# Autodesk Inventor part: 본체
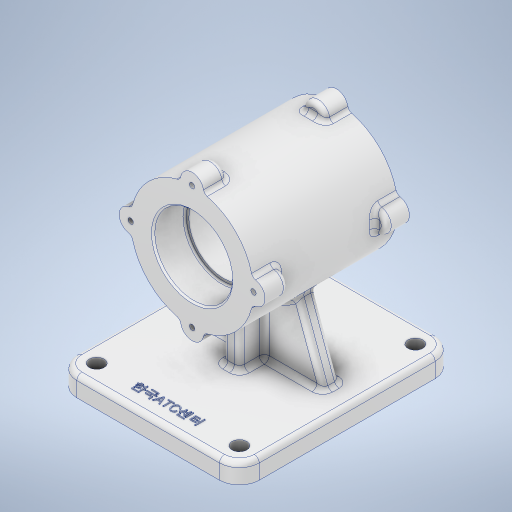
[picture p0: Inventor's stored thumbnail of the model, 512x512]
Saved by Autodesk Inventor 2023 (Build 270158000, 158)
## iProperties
Created: 2023-08
Part Number: 본체
Material: 알루미늄 6061
Document SubType Name: Modeling
Designer: asung
Density: 2.7 g/cm^3
Appearance: 알루미늄 - 평지
Mass: 1215.39 g
Surface Area: 796.917 cm^2
Volume: 450.145 cm^3
Author: asung
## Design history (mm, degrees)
sketch "스케치1"
  geometry: L1 (53, 55)-(-53, 55); L2 (-65, 43)-(-65, -43); L3 (-53, -55)-(53, -55); L4 (65, -43)-(65, 43); L5 (65, 55)-(-65, -55); L6 (-65, 55)-(65, -55); A1 r 12 centre (53, -43) between (53, -55) and (65, -43); A2 r 12 centre (53, 43) between (65, 43) and (53, 55); A3 r 12 centre (-53, 43) between (-53, 55) and (-65, 43); A4 r 12 centre (-53, -43) between (-65, -43) and (-53, -55); 1 further point
  constraints: 12 end point, 8 point on circle, 8 point on line, 8 tangent, 4 centre point, 3 equal radius, 2 midpoint, 2 parallel, 1 horizontal, 1 perpendicular
  dimensions: "d0" = 130 distance of L6.end L5.end; "d1" = 110 distance of L5.end L6.start; "d2" = 12 radius of A1
extrude "돌출1" new body sketch "스케치1" distance "d3" = 12; taper "d4" = 0 deg
fillet "모깎기1" dims "d5" = 3
sketch "스케치2"
  geometry: A1 r 9 centre (53, -43) between (53, -52) and (62, -43) reference; A2 r 9 centre (-53, -43) between (-62, -43) and (-53, -52) reference; A3 r 9 centre (-53, 43) between (-53, 52) and (-62, 43) reference; A4 r 9 centre (53, 43) between (62, 43) and (53, 52) reference; 5 further points
  constraints: 4 coincident
hole "구멍1" sketch "스케치2" at (53, -43), (-53, -43), (-53, 43), (53, 43) diameter "d6" = 9; stored, may be unused: countersink angle "d10" = 90 deg, drill point angle "d12" = 118 deg; dims "d7" = 6, "d8" = 4, "d9" = 2, "d11" = 8
node "작업 평면1"
sketch "스케치3"
  geometry: L1 (106, 0)-(0, 0) reference; L2 (58, 0)-(58, 82); L3 (-12, 0)-(-12, 9) reference; L4 (14.5, 82)-(101.5, 82); L5 (14.5, 82)-(14.5, 119); L6 (14.5, 119)-(101.5, 119); L7 (101.5, 119)-(101.5, 82); 1 further point
  constraints: 10 end point, 2 perpendicular, 2 vertical, 1 horizontal, 1 midpoint, 1 point on line
  dimensions: "d14" = 82 distance of L2.end L2.start; "d15" = 70 distance between parallel lines of L3 L2; "d16" = 87 distance of L4.start L4.end; "d17" = 37 distance of L4.start L5.end
revolve "회전1" sketch "스케치3" stored, may be unused: angle "d18" = 90 deg
node "작업 평면2"
sketch "스케치4"
  geometry: C1 r 37 at (0, 0) reference; C2 r 7 at (0, 37); 2 further points
  constraints: 1 centre point, 1 vertical alignment, 1 other
  dimensions: "d19" = 7 radius of C2
extrude "돌출2" join sketch "스케치4" distance "d23" = 14; taper "d24" = 0 deg
fillet "모깎기2" dims "d25" = 3
fillet "모깎기3" dims "d26" = 3
sketch "스케치5"
  geometry: A1 r 7 centre (0, 0) between (6.889, 1.239) and (-6.889, 1.239) reference; 2 further points
  constraints: 1 coincident
hole "구멍2" sketch "스케치5" at (0, 0) diameter "d27" = 3.242; stored, may be unused: countersink angle "d31" = 90 deg, drill point angle "d33" = 118 deg; dims "d28" = 8, "d29" = 4, "d30" = 2, "d32" = 10
sketch "스케치6"
  geometry: A1 r 37 centre (0, -37) between (-9.104, -1.137) and (-35.863, -27.896) reference; 2 further points
  constraints: 1 coincident
hole "구멍3" sketch "스케치6" at (0, -37) diameter "d37" = 42; stored, may be unused: countersink angle "d41" = 90 deg, drill point angle "d43" = 118 deg; dims "d38" = 8, "d39" = 47, "d40" = 19, "d42" = 10
sketch "스케치7"
  geometry: A1 r 37 centre (-37, 0) between (-1.138, 9.104) and (-27.896, 35.863) reference; 2 further points
  constraints: 1 coincident
hole "구멍4" sketch "스케치7" at (-37, 0) diameter "d44" = 42; stored, may be unused: countersink angle "d48" = 90 deg, drill point angle "d50" = 118 deg; dims "d45" = 6, "d46" = 47, "d47" = 19, "d49" = 8
fillet "모깎기4" dims "d51" = 1
chamfer "모따기1" distance "d52" = 1; stored, may be unused: second distance "d53" = 2, angle "d54" = 45 deg
sketch "스케치8"
  geometry: L1 (-52, -70)-(52, -70) reference; L2 (55, -73)-(55, -82) reference; L3 (55, -82)-(-55, -82) reference; L4 (-55, -82)-(-55, -73) reference; L5 (-41, -70)-(-25.336, -26.964); L6 (25.336, -26.964)-(41, -70); C1 r 21 at (0, 0) reference; A1 r 37 centre (0, 0) between (-25.336, -26.964) and (25.336, -26.964) reference; A2 r 3 centre (-52, -73) between (-52, -70) and (-55, -73) reference; A3 r 3 centre (52, -73) between (55, -73) and (52, -70) reference; 1 further point
  constraints: 4 end point, 2 point on circle, 2 point on line
  dimensions: "d55" = 110 deg angle of L1 L5; "d56" = 110 deg angle of L1 L6; "d57" = 14 distance from line of L4 L5.start; "d58" = 14 distance from line of L2 L6.end
extrude "돌출3" join sketch "스케치8" stored distance "d59" = 10; taper "d60" = 0 deg
sketch "스케치9"
  geometry: L1 (90.526, 45)-(91.5, 43.379) reference; L2 (91.5, 43.379)-(101.5, 43.379) reference; L3 (101.5, 43.379)-(101.5, 38) reference; L4 (101.5, 38)-(90.5, 38) reference; L5 (87.5, 41)-(87.5, 42) reference; L6 (84.5, 45)-(63, 45) reference; L7 (63, 45)-(63, 12) reference; L8 (63, 12)-(115, 12) reference; L9 (118, 9)-(118, 0) reference; L10 (118, 0)-(-12, 0) reference; L11 (-12, 0)-(-12, 9) reference; L12 (-9, 12)-(53, 12) reference; L13 (53, 12)-(53, 45) reference; L14 (53, 45)-(31.5, 45) reference; L15 (28.5, 42)-(28.5, 41) reference; L16 (25.5, 38)-(14.5, 38) reference; L17 (14.5, 38)-(14.5, 43.379) reference; L18 (14.5, 43.379)-(24.5, 43.379) reference; L19 (24.5, 43.379)-(25.474, 45) reference; L20 (25.474, 45)-(24.5, 46.621) reference; L21 (24.5, 46.621)-(14.5, 46.621) reference; L22 (14.5, 46.621)-(14.5, 57.5) reference; L23 (14.5, 57.5)-(15.5, 58.5) reference; L24 (15.5, 58.5)-(32.5, 58.5) reference; L25 (33.5, 59.5)-(33.5, 61) reference; L26 (33.5, 61)-(82.5, 61) reference; L27 (82.5, 61)-(82.5, 59.5) reference; L28 (83.5, 58.5)-(100.5, 58.5) reference; L29 (100.5, 58.5)-(101.5, 57.5) reference; L30 (101.5, 57.5)-(101.5, 46.621) reference; L31 (101.5, 46.621)-(91.5, 46.621) reference; L32 (91.5, 46.621)-(90.526, 45) reference; L33 (91.5, 120.621)-(90.526, 119) reference; L34 (90.526, 119)-(91.5, 117.379) reference; L35 (91.5, 117.379)-(101.5, 117.379) reference; L36 (101.5, 117.379)-(101.5, 106.5) reference; L37 (101.5, 106.5)-(100.5, 105.5) reference; L38 (100.5, 105.5)-(83.5, 105.5) reference; L39 (82.5, 104.5)-(82.5, 103) reference; L40 (82.5, 103)-(33.5, 103) reference; L41 (33.5, 103)-(33.5, 104.5) reference; L42 (32.5, 105.5)-(15.5, 105.5) reference; L43 (15.5, 105.5)-(14.5, 106.5) reference; L44 (14.5, 106.5)-(14.5, 117.379) reference; L45 (14.5, 117.379)-(24.5, 117.379) reference; L46 (24.5, 117.379)-(25.474, 119) reference; L47 (25.474, 119)-(24.5, 120.621) reference; L48 (24.5, 120.621)-(14.5, 120.621) reference; L49 (14.5, 120.621)-(14.5, 126) reference; L50 (14.5, 126)-(25.5, 126) reference; L51 (28.5, 123)-(28.5, 122) reference; L52 (31.5, 119)-(84.5, 119) reference; L53 (87.5, 122)-(87.5, 123) reference; L54 (90.5, 126)-(101.5, 126) reference; L55 (101.5, 126)-(101.5, 120.621) reference; L56 (101.5, 120.621)-(91.5, 120.621) reference; L57 (78, 4.5)-(38, 4.5); L58 (38, 4.5)-(38, 52.061); L59 (38, 52.061)-(78, 52.061); L60 (78, 52.061)-(78, 4.5); A1 r 3 centre (90.5, 41) between (87.5, 41) and (90.5, 38) reference; A2 r 3 centre (84.5, 42) between (87.5, 42) and (84.5, 45) reference; A3 r 3 centre (115, 9) between (118, 9) and (115, 12) reference; A4 r 3 centre (-9, 9) between (-9, 12) and (-12, 9) reference; A5 r 3 centre (31.5, 42) between (31.5, 45) and (28.5, 42) reference; A6 r 3 centre (25.5, 41) between (25.5, 38) and (28.5, 41) reference; A7 r 1 centre (32.5, 59.5) between (32.5, 58.5) and (33.5, 59.5) reference; A8 r 1 centre (83.5, 59.5) between (82.5, 59.5) and (83.5, 58.5) reference; A9 r 1 centre (83.5, 104.5) between (83.5, 105.5) and (82.5, 104.5) reference; A10 r 1 centre (32.5, 104.5) between (33.5, 104.5) and (32.5, 105.5) reference; A11 r 3 centre (25.5, 123) between (28.5, 123) and (25.5, 126) reference; A12 r 3 centre (31.5, 122) between (28.5, 122) and (31.5, 119) reference; A13 r 3 centre (84.5, 122) between (84.5, 119) and (87.5, 122) reference; A14 r 3 centre (90.5, 123) between (90.5, 126) and (87.5, 123) reference; 3 further points
  constraints: 8 end point, 2 midpoint, 2 parallel, 1 horizontal, 1 perpendicular, 1 vertical alignment
  dimensions: "d61" = 40 distance of L58.end L59.end
extrude "돌출4" join sketch "스케치9" stored distance "d62" = 10; taper "d63" = 0 deg
fillet "모깎기5" dims "d64" = 3
fillet "모깎기6" dims "d65" = 3
sketch "스케치10"
  geometry: L1 (13, -36.716)-(13, -8) reference; L2 (13, -8)-(22, -8) reference; L3 (28, -2)-(28, 2) reference; L4 (22, 8)-(13, 8) reference; L5 (13, 8)-(13, 36.716) reference; L6 (7, 43.101)-(3, 43.101) reference; L7 (-3, 36.716)-(-3, 8) reference; L8 (-3, 8)-(-12, 8) reference; L9 (-18, 2)-(-18, -2) reference; L10 (-12, -8)-(-3, -8) reference; L11 (-3, -8)-(-3, -36.716) reference; L12 (3, -43.101)-(7, -43.101) reference; L13 (53, 52)-(-53, 52) reference; L14 (-62, 43)-(-62, -43) reference; L15 (-53, -52)-(53, -52) reference; L16 (62, -43)-(62, 43) reference; C1 r 4.5 at (-53, 43) reference; C2 r 4.5 at (53, -43) reference; C3 r 4.5 at (-53, -43) reference; C4 r 4.5 at (53, 43) reference; A1 r 6 centre (22, -2) between (22, -8) and (28, -2) reference; A2 r 6 centre (22, 2) between (28, 2) and (22, 8) reference; A3 r 6 centre (-12, 2) between (-12, 8) and (-18, 2) reference; A4 r 6 centre (-12, -2) between (-18, -2) and (-12, -8) reference; A5 r 9 centre (53, 43) between (62, 43) and (53, 52) reference; A6 r 9 centre (-53, 43) between (-53, 52) and (-62, 43) reference; A7 r 9 centre (-53, -43) between (-62, -43) and (-53, -52) reference; A8 r 9 centre (53, -43) between (53, -52) and (62, -43) reference; 3 further points
  constraints: 1 horizontal alignment, 1 midpoint, 5 other
  dimensions: "d66" = 58 horizontal distance of point (-53, 0) point (5, -43.101)
feature "엠보싱1" sketch "스케치10" dims "d0" = 130, "d1" = 110, "d2" = 12, "d67" = 0.5, "d68" = 0
feature "Џ耀Б耀Г耀Е耀З耀Й耀Л耀Н耀" dims "d0" = 130, "d1" = 110, "d2" = 12, "d3" = 12, "d4" = 0, "d5" = 3, "d6" = 9, "d7" = 6, "d8" = 4, "d9" = 2, "d10" = 90 deg, "d11" = 8, "d12" = 118 deg, "d14" = 82, "d15" = 70, "d16" = 87, "d17" = 37, "d18" = 90 deg, "d19" = 7, "d23" = 14, "d24" = 0, "d25" = 3, "d26" = 3, "d27" = 3.242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
node "솔리드1"
pattern_circular "원형 패턴1" dims "d35" = 360 deg
mirror "미러1"
node "투영된 루프1"
node "절단 모서리 투영1"
node "절단 모서리 투영2"
node "절단 모서리 투영3"
feature "A9D066F2-1C7D-4E18-AEED-F7BC21143FA4" dims "d6" = 9, "d7" = 6, "d8" = 4, "d9" = 2, "d10" = 90 deg, "d11" = 8, "d12" = 118 deg
